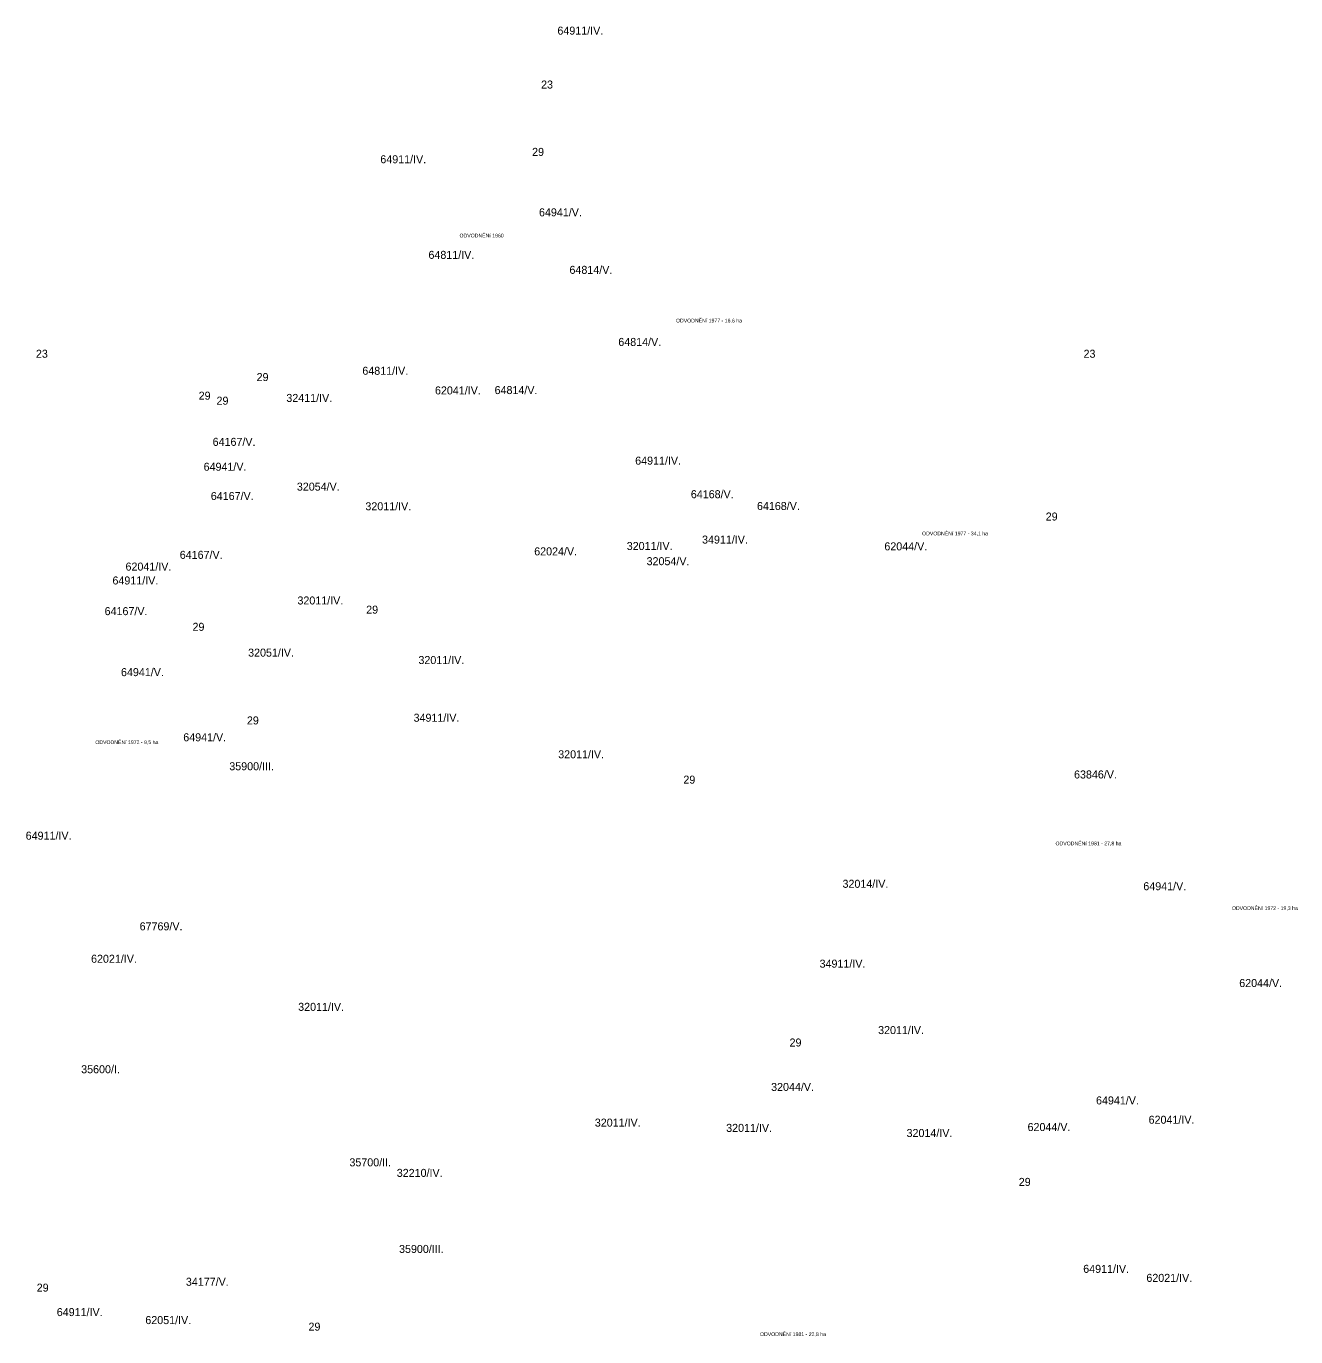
# Model space of a CAD drawing. Extents: x -521579 to -516881, y -1190081 to -1185166.
# Drawn here: x -519260 to -516881, y -1187622 to -1185166 of the extents above; entities that cross this region are included whole.
import ezdxf

# ---------------------------------------------------------------- set-up
doc = ezdxf.new("R2010")
doc.units = 0
doc.layers.add('BPEJ_s', color=7, linetype='Continuous')
doc.layers.add('odvodneni_s', color=7, linetype='Continuous')

msp = doc.modelspace()

# ---------------------------------------------------------------- texts
at = {"layer": 'BPEJ_s'}
for s, height, p in [('64911/IV.', 15, (-518264.8, -1185181.9)), ('23', 0.0647, (-517886.4, -1185188)), ('23', 15, (-518295.4, -1185282.9)), ('64911/IV.', 15, (-518596.6, -1185422.9)), ('29', 15, (-518312.2, -1185409.1)), ('64941/V.', 15, (-518299.3, -1185522.3)), ('64811/IV.', 15, (-518506.4, -1185602)), ('64814/V.', 15, (-518242.2, -1185630.1)), ('64814/V.', 15, (-518150.7, -1185765.2)), ('23', 15, (-519241.9, -1185787.3)), ('23', 15, (-517279, -1185787.3)), ('29', 15, (-518828.4, -1185831)), ('64811/IV.', 15, (-518630.3, -1185819.2)), ('62041/IV.', 15, (-518494.2, -1185856)), ('64814/V.', 15, (-518382.5, -1185855.4)), ('29', 15, (-518937, -1185865.9)), ('29', 15, (-518903.5, -1185875.3)), ('32411/IV.', 15, (-518772.7, -1185870.1)), ('35', 0.0647, (-518551.9, -1185894.1)), ('29', 0.0647, (-518159.4, -1185899)), ('64167/V.', 15, (-518910.8, -1185952.4)), ('64911/IV.', 15, (-518119.1, -1185987.6)), ('64941/V.', 15, (-518927.7, -1185999)), ('32054/V.', 15, (-518753, -1186036.3)), ('64167/V.', 15, (-518914.2, -1186053.8)), ('64168/V.', 15, (-518014.8, -1186050.5)), ('32011/IV.', 15, (-518624.6, -1186073.1)), ('64168/V.', 15, (-517890.9, -1186072.6)), ('29', 15, (-517349.9, -1186092.3)), ('34911/IV.', 15, (-517993.8, -1186135.5)), ('62024/V.', 15, (-518308.3, -1186157.6)), ('32011/IV.', 15, (-518134.9, -1186147.5)), ('62044/V.', 15, (-517652.2, -1186148.2)), ('64167/V.', 15, (-518972.4, -1186164.1)), ('32054/V.', 15, (-518097.7, -1186176)), ('62041/IV.', 15, (-519074, -1186186.1)), ('64911/IV.', 15, (-519098.5, -1186212.1)), ('32011/IV.', 15, (-518751.9, -1186249.6)), ('64167/V.', 15, (-519113.2, -1186269.6)), ('29', 15, (-518623.1, -1186266.8)), ('29', 15, (-518948.5, -1186298.9)), ('32051/IV.', 15, (-518844.3, -1186347.3)), ('32011/IV.', 15, (-518525.2, -1186361.2)), ('64941/V.', 15, (-519082.5, -1186383.9)), ('29', 15, (-518846.6, -1186474.3)), ('34911/IV.', 15, (-518534.3, -1186469.3)), ('64941/V.', 15, (-518965.8, -1186505.9)), ('32011/IV.', 15, (-518263.3, -1186537.8)), ('35900/III.', 15, (-518879.6, -1186560.2)), ('63846/V.', 15, (-517296.8, -1186575.6)), ('29', 15, (-518028.8, -1186585.3)), ('64911/IV.', 15, (-519261.1, -1186690.3)), ('32014/IV.', 15, (-517730.6, -1186780.4)), ('64941/V.', 15, (-517167, -1186785)), ('67769/V.', 15, (-519047.6, -1186860.1)), ('62021/IV.', 15, (-519138.6, -1186920.9)), ('34911/IV.', 15, (-517773.6, -1186930.1)), ('62044/V.', 15, (-516987.3, -1186966.4)), ('32011/IV.', 15, (-518750.5, -1187011)), ('32011/IV.', 15, (-517663.9, -1187054.5)), ('29', 15, (-517829.8, -1187077.8)), ('35600/I.', 15, (-519157.1, -1187127.9)), ('32044/V.', 15, (-517864.4, -1187161.1)), ('64941/V.', 15, (-517255.6, -1187186.3)), ('32011/IV.', 15, (-518194.7, -1187227.9)), ('32011/IV.', 15, (-517948.6, -1187237.8)), ('62044/V.', 15, (-517383.9, -1187236.2)), ('62041/IV.', 15, (-517157.1, -1187222.5)), ('32014/IV.', 15, (-517610.6, -1187247.4)), ('35700/II.', 15, (-518654.5, -1187302.3)), ('32210/IV.', 15, (-518565.8, -1187322.1)), ('29', 15, (-517400.4, -1187339)), ('35900/III.', 15, (-518561.5, -1187464.6)), ('64911/IV.', 15, (-517279.6, -1187501.9)), ('34177/V.', 15, (-518960.9, -1187526.1)), ('62021/IV.', 15, (-517161.3, -1187518.8)), ('29', 15, (-519240.4, -1187537.1)), ('64911/IV.', 15, (-519202.8, -1187582.9)), ('62051/IV.', 15, (-519036.9, -1187597.9)), ('29', 15, (-518731.2, -1187610.2))]:
    msp.add_text(s, height=height, dxfattribs=at).set_placement(p)
at = {"layer": 'odvodneni_s'}
for s, p in [('ODVODNĚNí 1960', (-518448.2, -1185561.9)), ('ODVODNĚNí 1977 - 16,6 ha', (-518042.6, -1185721.2)), ('ODVODNĚNí 1977 - 34,1 ha', (-517581.5, -1186120)), ('ODVODNĚNí 1972 - 9,5 ha', (-519130.6, -1186511.2)), ('ODVODNĚNí 1981 - 27,8 ha', (-517331.5, -1186700.8)), ('ODVODNĚNí 1972 - 19,3 ha', (-517001, -1186822)), ('ODVODNĚNí 1981 - 22,8 ha', (-517885.2, -1187620.4))]:
    msp.add_text(s, height=7, dxfattribs=at).set_placement(p)

doc.saveas('drawing.dxf')
